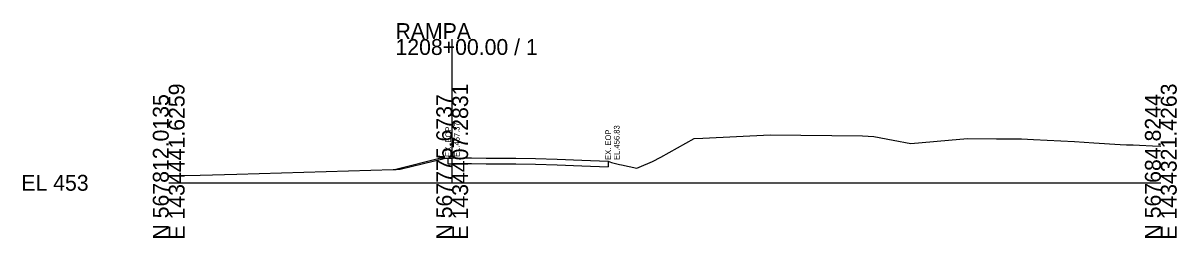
# Model space of a CAD drawing. Extents: x 1431908 to 1449087, y 567604 to 577825.
# Drawn here: x 1432908 to 1433111.5, y 574352.5 to 574390.3 of the extents above; entities that cross this region are included whole.
import ezdxf

# ---------------------------------------------------------------- set-up
doc = ezdxf.new("R2010")
doc.units = 0
for name, color, linetype in [('DESIGN - SHEET - Light Grid', 7, 'Continuous'), ('DESIGN - TYPICAL - Finished Grade and Subgrade', 7, 'Continuous'), ('SURVEY - GROUND - Existing Pavement Layer', 7, 'Continuous'), ('SURVEY - GROUND - Existing Pavement Text', 7, 'Continuous'), ('SURVEY - GROUND - Top of Ground', 7, 'Continuous')]:
    doc.layers.add(name, color=color, linetype=linetype)

msp = doc.modelspace()

# ---------------------------------------------------------------- linework, layer by layer
at = {"layer": 'DESIGN - SHEET - Light Grid'}
for p, q in [((1432983.66, 574362.16), (1432983.66, 574387.47)), ((1432933.66, 574362.16), (1432983.66, 574362.16)), ((1432983.66, 574362.16), (1433108.66, 574362.16))]:
    msp.add_line(p, q, dxfattribs=at)
at = {"layer": 'DESIGN - TYPICAL - Finished Grade and Subgrade'}
for q in [(1432973.7, 574364.53), (1432986.21, 574366.53)]:
    msp.add_line((1432981.66, 574366.52), q, dxfattribs=at)
at = {"layer": 'SURVEY - GROUND - Existing Pavement Layer'}
for p, q in [((1432982.97, 574365.52), (1432982.97, 574366.52)), ((1432982.97, 574365.52), (1432983.66, 574365.52)), ((1432983.66, 574365.52), (1432986.21, 574365.53)), ((1432986.21, 574365.53), (1432987.08, 574365.53)), ((1432987.08, 574365.53), (1432989.66, 574365.52)), ((1432989.66, 574365.52), (1432994.91, 574365.5)), ((1432994.91, 574365.5), (1432998.34, 574365.42)), ((1432998.34, 574365.42), (1433002.2, 574365.33)), ((1433002.2, 574365.33), (1433006.51, 574365.17)), ((1433006.51, 574365.17), (1433011.18, 574364.99)), ((1433011.18, 574365.99), (1433011.18, 574364.99))]:
    msp.add_line(p, q, dxfattribs=at)
at = {"layer": 'SURVEY - GROUND - Top of Ground'}
msp.add_lwpolyline([(1432933.66, 574363.36), (1432939.22, 574363.52), (1432945.66, 574363.7), (1432973.24, 574364.52), (1432973.76, 574364.53), (1432974.49, 574364.57), (1432976.43, 574365.03), (1432982.46, 574366.47), (1432982.97, 574366.52), (1432983.66, 574366.52), (1432986.21, 574366.53), (1432987.08, 574366.53), (1432989.66, 574366.52), (1432994.91, 574366.5), (1432998.34, 574366.42), (1433002.2, 574366.33), (1433006.51, 574366.17), (1433011.18, 574365.99), (1433011.75, 574365.76), (1433013.18, 574365.38), (1433013.55, 574365.3), (1433016.23, 574364.75), (1433016.67, 574364.91), (1433019.01, 574365.9), (1433020.47, 574366.65), (1433026.36, 574369.97), (1433027.89, 574370.02), (1433039.76, 574370.6), (1433056.03, 574370.41), (1433058.06, 574370.32), (1433061.42, 574369.68), (1433064.59, 574369.07), (1433073.2, 574369.86), (1433074.59, 574369.97), (1433079.66, 574369.93), (1433084.09, 574369.91), (1433086.23, 574369.8), (1433093.45, 574369.44), (1433096.82, 574369.21), (1433101.49, 574368.9), (1433102.59, 574368.83), (1433103.76, 574368.82), (1433104.89, 574368.8), (1433107.22, 574368.66), (1433108.66, 574368.62)], dxfattribs=at)

# ---------------------------------------------------------------- texts
at = {"layer": 'DESIGN - SHEET - Light Grid'}
for s, p in [('RAMPA', (1432973.66, 574387.47)), ('1208+00.00 / 1', (1432973.66, 574384.67)), ('EL 453', (1432907.66, 574360.76))]:
    msp.add_text(s, height=2.8, dxfattribs=at).set_placement(p)
for s, p in [('E 1434441.6259', (1432936.46, 574352.16)), ('E 1434407.2831', (1432986.46, 574352.16)), ('E 1434321.4263', (1433111.46, 574352.16)), ('N 567812.0135', (1432933.66, 574352.16)), ('N 567775.6737', (1432983.66, 574352.16)), ('N 567684.8244', (1433108.66, 574352.16))]:
    msp.add_text(s, height=2.8, rotation=90, dxfattribs=at).set_placement(p)
at = {"layer": 'SURVEY - GROUND - Existing Pavement Text'}
for s, p in [('EX. EOP', (1432983.47, 574366.72)), ('EL.457.37', (1432984.97, 574366.72)), ('EX. EOP', (1433011.68, 574366.19)), ('EL.456.83', (1433013.18, 574366.19))]:
    msp.add_text(s, height=1, rotation=90, dxfattribs=at).set_placement(p)

doc.saveas('drawing.dxf')
